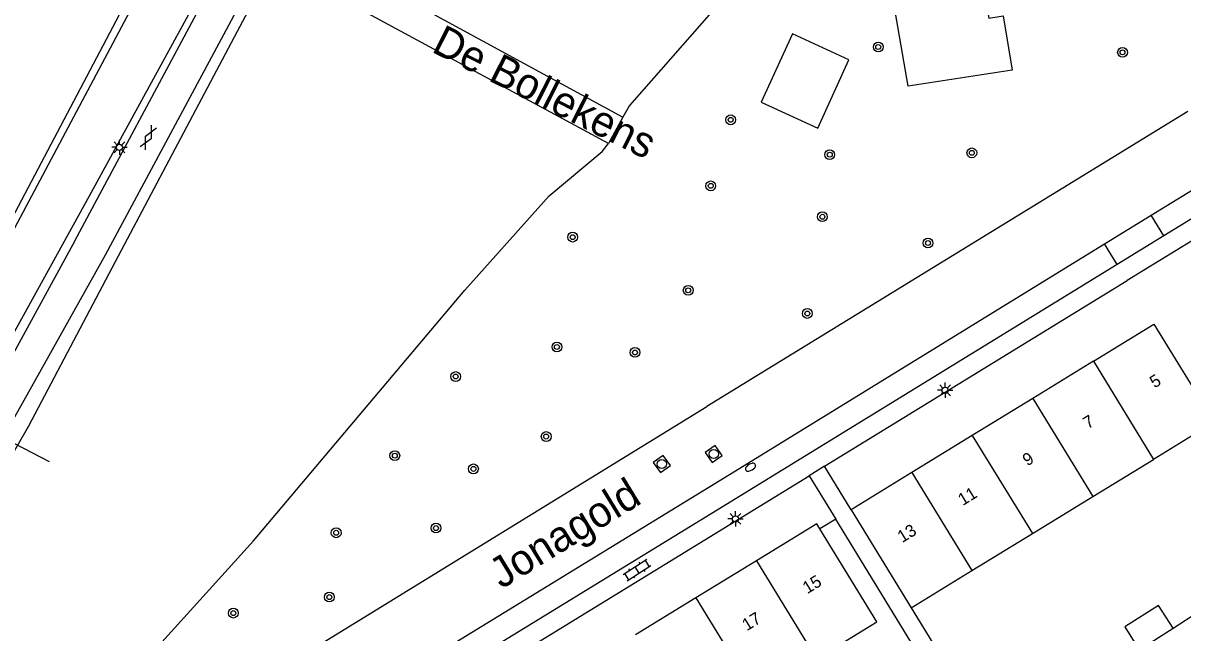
# Model space of a CAD drawing. Extents: x 136000 to 138005, y 398500 to 400500.
# Drawn here: x 137066.8 to 137161.5, y 398910.9 to 398960.7 of the extents above; entities that cross this region are included whole.
import ezdxf

# ---------------------------------------------------------------- set-up
doc = ezdxf.new("R2010")
doc.units = 0
for name, color, linetype in [('gg-afsc-erfafscheiding', 7, 'Continuous'), ('gg-anno-huisnummerreeks BGT', 7, 'Continuous'), ('gg-anno-openbare ruimte label', 7, 'Continuous'), ('gg-bbg-bijgebouw', 7, 'Continuous'), ('gg-bbg-hoofdgebouw', 7, 'Continuous'), ('gg-bbg-tussenscheiding', 7, 'Continuous'), ('gg-knt-BGT kruinlijn', 7, 'Continuous'), ('gg-knt-bovenkant onderkant talud', 7, 'Continuous'), ('gg-knt-verharding', 7, 'Continuous'), ('gg-knt-verharding nz', 7, 'Continuous'), ('gg-kntw-bovenkant insteek waterloop', 7, 'Continuous'), ('gg-kwrk-duiker nz buis', 7, 'Continuous'), ('gg-kwrk-kunstwerk niveau 01', 7, 'Continuous'), ('gt-grn-weggrens', 7, 'Continuous'), ('gt-symb-boom', 7, 'Continuous'), ('gt-symb-brandkraan', 7, 'Continuous'), ('gt-symb-gesloten verharding', 7, 'Continuous'), ('gt-symb-klinker verharding', 7, 'Continuous'), ('gt-symb-lichtmast', 7, 'Continuous'), ('gt-symb-rioolschacht', 7, 'Continuous')]:
    doc.layers.add(name, color=color, linetype=linetype)

# ---------------------------------------------------------------- blocks, each defined once
blk = doc.blocks.new('gt0-LMAST')
at = {"layer": 'gt-symb-lichtmast'}
for p, q in [((-0.182, 0.173), (-0.447, 0.438)), ((-0.005, 0.246), (-0.005, 0.621)), ((0.172, 0.173), (0.437, 0.438)), ((-0.255, -0.004), (-0.63, -0.004)), ((-0.182, -0.181), (-0.447, -0.446)), ((-0.005, -0.254), (-0.005, -0.629)), ((0.437, -0.446), (0.172, -0.181)), ((0.245, -0.004), (0.62, -0.004))]:
    blk.add_line(p, q, dxfattribs=at)
blk.add_circle((-0.005, -0.004), 0.25, dxfattribs=at)
blk = doc.blocks.new('gt0-RS')
at = {"layer": 'gt-symb-rioolschacht'}
blk.add_lwpolyline([(-0.5, -0.5), (0.5, -0.5), (0.5, 0.5), (-0.5, 0.5)], close=True, dxfattribs=at)
blk.add_circle((0, 0), 0.375, dxfattribs=at)
blk = doc.blocks.new('gt0-BR')
at = {"layer": 'gt-symb-brandkraan'}
for centre, radius, start, end in [((-0.244, 0), 0.206, 107.56694, 252.43307), ((0.599, -2.664), 3, 106.89205, 107.56694), ((0, -0.691), 0.938, 73.10799, 106.89205), ((-0.599, -2.664), 3, 72.43309, 73.10799), ((0.244, 0), 0.206, 287.56695, 72.43309), ((0.599, 2.664), 3, 252.43307, 253.10797), ((0, 0.691), 0.938, 253.10797, 286.89206), ((-0.599, 2.664), 3, 286.89206, 287.56695)]:
    blk.add_arc(centre, radius, start, end, dxfattribs=at)
blk = doc.blocks.new('gt0-BOOM')
at = {"layer": 'gt-symb-boom'}
for radius in [0.4, 0.2]:
    blk.add_circle((0, 0), radius, dxfattribs=at)
blk = doc.blocks.new('gt0-KL1')
at = {"layer": 'gt-symb-klinker verharding'}
for p, q in [((-1.15, 0.3), (1.15, 0.3)), ((-1, -0.3), (-1, 0.3)), ((-0.5, 0.3), (-0.5, 0.45)), ((0, -0.3), (0, 0.3)), ((0.5, 0.3), (0.5, 0.45)), ((1, -0.3), (1, 0.3)), ((-1.15, -0.3), (1.15, -0.3)), ((-0.5, -0.45), (-0.5, -0.3)), ((0.5, -0.45), (0.5, -0.3))]:
    blk.add_line(p, q, dxfattribs=at)
blk = doc.blocks.new('gt0-GESVH1')
at = {"layer": 'gt-symb-gesloten verharding'}
for p, q in [((-0.992, -0.261), (0.008, 0.239)), ((0.008, -0.261), (-0.992, 0.239)), ((0.008, 0.239), (1.008, -0.261)), ((1.008, 0.239), (0.008, -0.261))]:
    blk.add_line(p, q, dxfattribs=at)

msp = doc.modelspace()

# ---------------------------------------------------------------- linework, layer by layer
at = {"layer": 'gg-afsc-erfafscheiding'}
for p, q in [((137133.149, 398920.192), (137131.846, 398919.42)), ((137160.67, 398911.31), (137162.779, 398912.661))]:
    msp.add_line(p, q, dxfattribs=at)
for points in [[(137140.05, 398900.874), (137142.693, 398902.584), (137143.069, 398903.976), (137133.149, 398920.192)], [(137139.297, 398912.973), (137144.388, 398904.677), (137145.803, 398904.307), (137147.255, 398905.193)]]:
    msp.add_lwpolyline(points, dxfattribs=at)
at = {"layer": 'gg-bbg-bijgebouw'}
msp.add_line((137157.892, 398909.543), (137160.67, 398911.31), dxfattribs=at)
msp.add_lwpolyline([(137160.67, 398911.31), (137159.49, 398913.167), (137156.735, 398911.413), (137157.892, 398909.543)], dxfattribs=at)
at = {"layer": 'gg-bbg-hoofdgebouw'}
for p, q in [((137154.166, 398933.082), (137149.224, 398930.054)), ((137149.224, 398930.054), (137144.281, 398927.027)), ((137144.281, 398927.027), (137139.339, 398923.999)), ((137154.124, 398922.056), (137159.066, 398925.084)), ((137139.339, 398923.999), (137134.397, 398920.971)), ((137149.181, 398919.029), (137154.124, 398922.056)), ((137134.397, 398920.971), (137139.297, 398912.973)), ((137144.239, 398916.001), (137149.181, 398919.029)), ((137126.655, 398916.807), (137121.717, 398913.781)), ((137139.297, 398912.973), (137144.239, 398916.001)), ((137121.717, 398913.781), (137116.778, 398910.755))]:
    msp.add_line(p, q, dxfattribs=at)
for points in [[(137154.166, 398933.082), (137159.108, 398936.11), (137164.008, 398928.112), (137159.066, 398925.084)], [(137131.846, 398919.42), (137131.593, 398919.833), (137126.655, 398916.807)], [(137131.553, 398908.81), (137136.491, 398911.833), (137131.846, 398919.42)]]:
    msp.add_lwpolyline(points, dxfattribs=at)
at = {"layer": 'gg-bbg-tussenscheiding'}
for p, q in [((137154.166, 398933.082), (137159.066, 398925.084)), ((137149.224, 398930.054), (137154.124, 398922.056)), ((137144.281, 398927.027), (137149.181, 398919.029)), ((137139.339, 398923.999), (137144.239, 398916.001)), ((137126.655, 398916.807), (137131.553, 398908.81)), ((137121.717, 398913.781), (137126.615, 398905.787))]:
    msp.add_line(p, q, dxfattribs=at)
at = {"layer": 'gg-knt-BGT kruinlijn'}
msp.add_lwpolyline([(137056.607, 398927.27), (137064.979, 398941.818), (137081.964, 398973.774), (137098.123, 399004.102), (137112.07, 399030.206), (137125.592, 399055.865), (137140.065, 399083.946), (137153.096, 399111.604), (137165.37, 399137.346), (137164.155, 399139.723), (137161.927, 399143.986), (137161.529, 399143.706), (137164.252, 399137.415), (137139.432, 399084.215), (137124.979, 399056.265), (137111.263, 399030.458), (137097.52, 399004.494), (137081.276, 398973.964), (137064.523, 398942.202), (137056.05, 398927.467)], dxfattribs=at)
at = {"layer": 'gg-knt-bovenkant onderkant talud'}
msp.add_lwpolyline([(137169.226, 399136.854), (137165.158, 399127.247), (137153.803, 399103.121), (137140.161, 399074.983), (137123.856, 399043.837), (137108.502, 399015.017), (137098.636, 398996.361), (137085.798, 398971.447), (137072.186, 398946.553), (137059.363, 398923.378), (137053.196, 398911.951)], dxfattribs=at)
at = {"layer": 'gg-knt-verharding'}
for p, q in [((137161.869, 398953.468), (137122.598, 398929.384)), ((137174.67, 398950.556), (137156.921, 398939.682)), ((137159.925, 398943.321), (137156.116, 398940.982)), ((137156.102, 398940.973), (137156.116, 398940.982)), ((137132.222, 398924.524), (137156.921, 398939.682)), ((137073.74, 398899.369), (137122.598, 398929.384)), ((137080.272, 398892.675), (137130.968, 398923.751)), ((137130.968, 398923.751), (137133.149, 398920.192)), ((137134.397, 398920.971), (137132.222, 398924.524))]:
    msp.add_line(p, q, dxfattribs=at)
for points in [[(137071.016, 398942.91), (137081.171, 398961.853), (137091.527, 398981.243), (137102.156, 399001.389), (137112.465, 399020.975), (137132.096, 399057.931), (137142.439, 399078.092), (137147.799, 399089.19), (137151.644, 399097.313), (137160.531, 399116.289), (137172.818, 399142.752), (137172.98, 399145.003)], [(137147.537, 398956.832), (137139.05, 398955.538), (137137.416, 398964.984), (137144.737, 398966.308), (137145.616, 398961.085), (137146.796, 398961.268), (137147.537, 398956.832)], [(137086.5, 398966.027), (137083.552, 398960.473), (137073.49, 398941.755)], [(137131.663, 398952.097), (137134.206, 398957.677), (137129.597, 398959.81), (137127.054, 398954.23), (137131.663, 398952.097)], [(137168.876, 398951.135), (137169.948, 398949.476), (137159.925, 398943.321)], [(137071.016, 398942.91), (137060.627, 398923.938), (137058.577, 398920.164)], [(137073.49, 398941.755), (137063.525, 398923.969), (137061.197, 398919.726)], [(137156.102, 398940.973), (137123.804, 398921.155), (137079.535, 398894.033)]]:
    msp.add_lwpolyline(points, dxfattribs=at)
at = {"layer": 'gg-knt-verharding nz'}
for p, q in [((137158.891, 398945.003), (137168.876, 398951.135)), ((137155.083, 398942.664), (137158.891, 398945.003)), ((137159.925, 398943.321), (137158.891, 398945.003)), ((137124.453, 398923.854), (137155.083, 398942.664)), ((137156.116, 398940.982), (137155.083, 398942.664)), ((137077.457, 398895.072), (137124.453, 398923.854))]:
    msp.add_line(p, q, dxfattribs=at)
at = {"layer": 'gg-kntw-bovenkant insteek waterloop'}
for points in [[(137138.344, 398979.073), (137116.298, 398953.969), (137115.762, 398953.012)], [(137087.266, 398965.613), (137084.274, 398960.001), (137074.321, 398941.213)], [(137074.254, 398905.896), (137085.612, 398918.424), (137102.861, 398938.898), (137109.741, 398946.591), (137114.075, 398950.211), (137114.586, 398950.866)], [(137074.321, 398941.213), (137067.245, 398927.788), (137062.114, 398918.913)]]:
    msp.add_lwpolyline(points, dxfattribs=at)
at = {"layer": 'gg-kwrk-duiker nz buis'}
msp.add_line((137068.957, 398924.882), (137049.607, 398934.929), dxfattribs=at)
at = {"layer": 'gg-kwrk-kunstwerk niveau 01'}
for p, q in [((137088.458, 398967.849), (137115.762, 398953.012)), ((137114.586, 398950.866), (137087.266, 398965.613)), ((137115.762, 398953.012), (137114.586, 398950.866))]:
    msp.add_line(p, q, dxfattribs=at)
at = {"layer": 'gt-grn-weggrens'}
msp.add_line((137132.222, 398924.524), (137130.968, 398923.751), dxfattribs=at)

# ---------------------------------------------------------------- block references
at = {"layer": 'gt-symb-boom'}
for p in [(137136.602, 398958.734), (137156.541, 398958.293), (137124.555, 398952.787), (137132.643, 398949.948), (137144.242, 398950.092), (137122.93, 398947.4), (137132.043, 398944.879), (137111.661, 398943.216), (137140.658, 398942.733), (137121.09, 398938.878), (137130.812, 398936.987), (137110.371, 398934.255), (137116.743, 398933.809), (137102.11, 398931.84), (137109.498, 398926.942), (137097.139, 398925.385), (137103.559, 398924.304), (137092.352, 398919.092), (137100.497, 398919.475), (137091.798, 398913.843), (137083.962, 398912.537)]:
    msp.add_blockref('gt0-BOOM', p, dxfattribs=at)
at = {"layer": 'gt-symb-brandkraan', "rotation": 30.73679989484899}
msp.add_blockref('gt0-BR', (137126.177, 398924.441), dxfattribs=at)
at = {"layer": 'gt-symb-gesloten verharding', "rotation": 62.8202657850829}
msp.add_blockref('gt0-GESVH1', (137077.007, 398951.35), dxfattribs=at)
at = {"layer": 'gt-symb-klinker verharding', "rotation": 32.70422579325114}
msp.add_blockref('gt0-KL1', (137116.912, 398916.053), dxfattribs=at)
at = {"layer": 'gt-symb-lichtmast'}
for p in [(137074.668, 398950.547), (137142.067, 398930.725), (137124.953, 398920.231)]:
    msp.add_blockref('gt0-LMAST', p, dxfattribs=at)
at = {"layer": 'gt-symb-rioolschacht'}
for p, rotation in [((137123.177, 398925.523), 34.91665541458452), ((137118.937, 398924.706), 35.28158067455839)]:
    msp.add_blockref('gt0-RS', p, dxfattribs=dict(at, rotation=rotation))

# ---------------------------------------------------------------- texts
at = {"layer": 'gg-anno-huisnummerreeks BGT'}
for s, p in [('5', (137159.151, 398930.859)), ('7', (137153.714, 398927.528)), ('9', (137148.772, 398924.501)), ('11', (137143.499, 398921.27)), ('13', (137138.557, 398918.242)), ('15', (137130.813, 398914.077)), ('17', (137125.875, 398911.051))]:
    msp.add_text(s, height=1, rotation=31.5, dxfattribs=at).set_placement(p)
at = {"layer": 'gg-anno-openbare ruimte label'}
for s, rotation, p in [('De Bollekens', 333.3, (137100.044, 398958.382)), ('Jonagold', 31.5, (137105.846, 398914.463))]:
    msp.add_text(s, height=2.5, rotation=rotation, dxfattribs=at).set_placement(p)

doc.saveas('drawing.dxf')
